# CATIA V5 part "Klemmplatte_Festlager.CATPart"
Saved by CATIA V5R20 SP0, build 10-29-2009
Part number: Klemmplatte_Festlager
Bounding box of the stored display mesh (mm): x -28.8 to 28.8, y -28.8 to 28.8, z 0 to 2
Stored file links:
  C:\Users\Andi\Desktop\Offene Projekte\Plasmacutter\Z-Achse\Klemmplatte_Festlager.CATPart
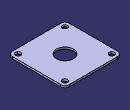
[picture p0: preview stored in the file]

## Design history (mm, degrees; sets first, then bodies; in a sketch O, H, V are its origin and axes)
Body1 (main body)
  Sketch1 on xy-plane, origin (0, 0, 0), H (1, 0, 0), V (0, 1, 0)
    line L1 (29, 24) -> (29, -24)
    line L2 (24, -29) -> (-24, -29)
    line L3 (-29, -24) -> (-29, 24)
    line L4 (-24, 29) -> (24, 29)
    arc A1 centre (24, 24) radius 5 from (29, 24) to (24, 29) ccw
    arc A2 centre (24, -24) radius 5 from (29, -24) to (24, -29) cw
    arc A3 centre (-24, -24) radius 5 from (-24, -29) to (-29, -24) cw
    arc A4 centre (-24, 24) radius 5 from (-29, 24) to (-24, 29) cw
    circle A5 centre (0, 0) radius 8.5
    distance L2 L4 = 58
    distance L1 L3 = 58
    radius A1 = 5
    radius A2 = 5 {= Sketch1.radius(A1)}
    radius A3 = 5 {= Sketch1.radius(A1)}
    radius A4 = 5 {= Sketch1.radius(A1)}
    radius A5 = 8.5
    vertical: L1 V, L3 V
    horizontal: L2 H, L4 H
    equidistance: L1 L3 O, L2 L4 O
    tangency: A1 L1, A1 L4, A2 L1, A2 L2, A3 L2, A3 L3, A4 L3, A4 L4
  Pad1: profile Sketch1, direction (0, 0, 1), length 2
  Sketch2 on end face of Pad1, origin (-21.6902, -22.2196, 2), H (1, 0, 0), V (0, 1, 0)
    point P1 (-1.8798, -1.3504)
    reference intersected line E1 through (21.6902, 0) direction (0, 1) from yz-plane
    reference intersected line E2 through (0, 22.2196) direction (-1, 0) from zx-plane
    distance P1 E1 = 23.57
    distance P1 E2 = 23.57 {= Sketch2.distance(P1 E1)}
  Hole1: placed by Sketch2, at (-23.57, -23.57, 2) direction (0, 0, -1), diameter 5.3, through (limit type 6)
  CircPattern1: of Hole1, instances 4, angular step 90 {= 360.0*1 deg/CircPattern1.AngularNumber}, axis from face of Pad1 from Sketch1.A5
  Thickness1: Thickness -0.2, Face face of Pad1 from Sketch1.L4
